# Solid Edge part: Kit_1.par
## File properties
Sűrűség: 0,000 kg/m^3
Pontosság: 0,990
Author: ahadarics
Last saved by: ahadarics
Revision: 76
Username: ahadarics
Dokumentum tartalom típus: 0
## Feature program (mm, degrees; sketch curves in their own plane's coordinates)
base feature "unnamed BaseFeature 1"
sketch for "Furat_1" plane through (0, -49.25, 13.5) normal (0, 0, 1) x-axis (0, 1, 0)
  hole centre (0.25, 0) bore radius 4.283
hole "Furat_1" nominal diameter 9.728 finite  ThreadDepth = 7.5 mm
chamfer "Letörés_1" setback 0.7
thread "unnamed Thread 1"
chamfer "Letörés_2" setback 1.5
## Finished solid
Body 1: solid body, 49 faces, 55 edges, 9 vertices.
  Faces by surface: cylinder 16, plane 15, cone 11, torus 7
  Edges by curve: circle 46, line 7, intersection 2
Bounding box of the edges (mm; curved faces can reach further): 30.000 x 39.500 x 28.500, from (-15, -79, -15) to (15, -39.5, 13.5).
Cylindrical faces by radius (mm): R4.283 x3, R5.25 x1, R5.55 x1, R7 x3, R7.05 x1, R8.05 x1, R8.1 x1, R9.85 x1, R11 x2, R13.5 x1, R15 x1
Conical faces (half-angle, radius in mm at the cone's reference point): 0.1788 deg R6.7706 x1, 15 deg R8.05 x1, 17.2279 deg R5.55 x1, 19.7315 deg R5.0176 x1, 21.0856 deg R5.55 x1, 21.5244 deg R6.2703 x1, 45 deg R4.283 x1, 45 deg R7.15 x1, 45 deg R7.2 x1, 45 deg R11 x1, 60 deg R10.425 x1
Toroidal faces (ring radius, tube radius in mm): R5.2 r0.2 x1, R5.3 r0.3 x1, R6.6424 r0.4 x1, R6.85 r0.2 x1, R7.85 r0.2 x1, R7.9 r0.2 x2
Planar faces by outward normal: +y 5, +z 2, -y 8
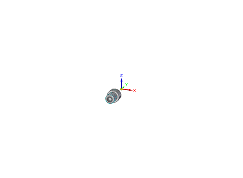
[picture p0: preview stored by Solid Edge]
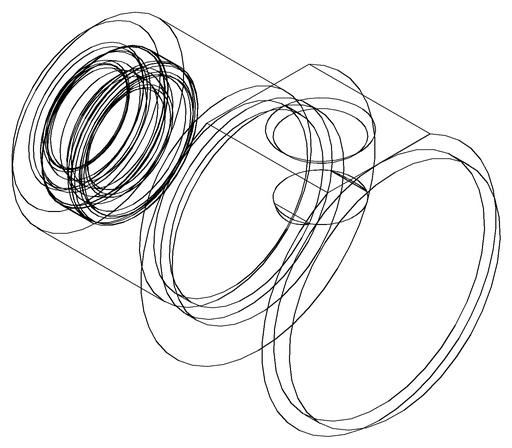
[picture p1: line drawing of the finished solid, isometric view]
